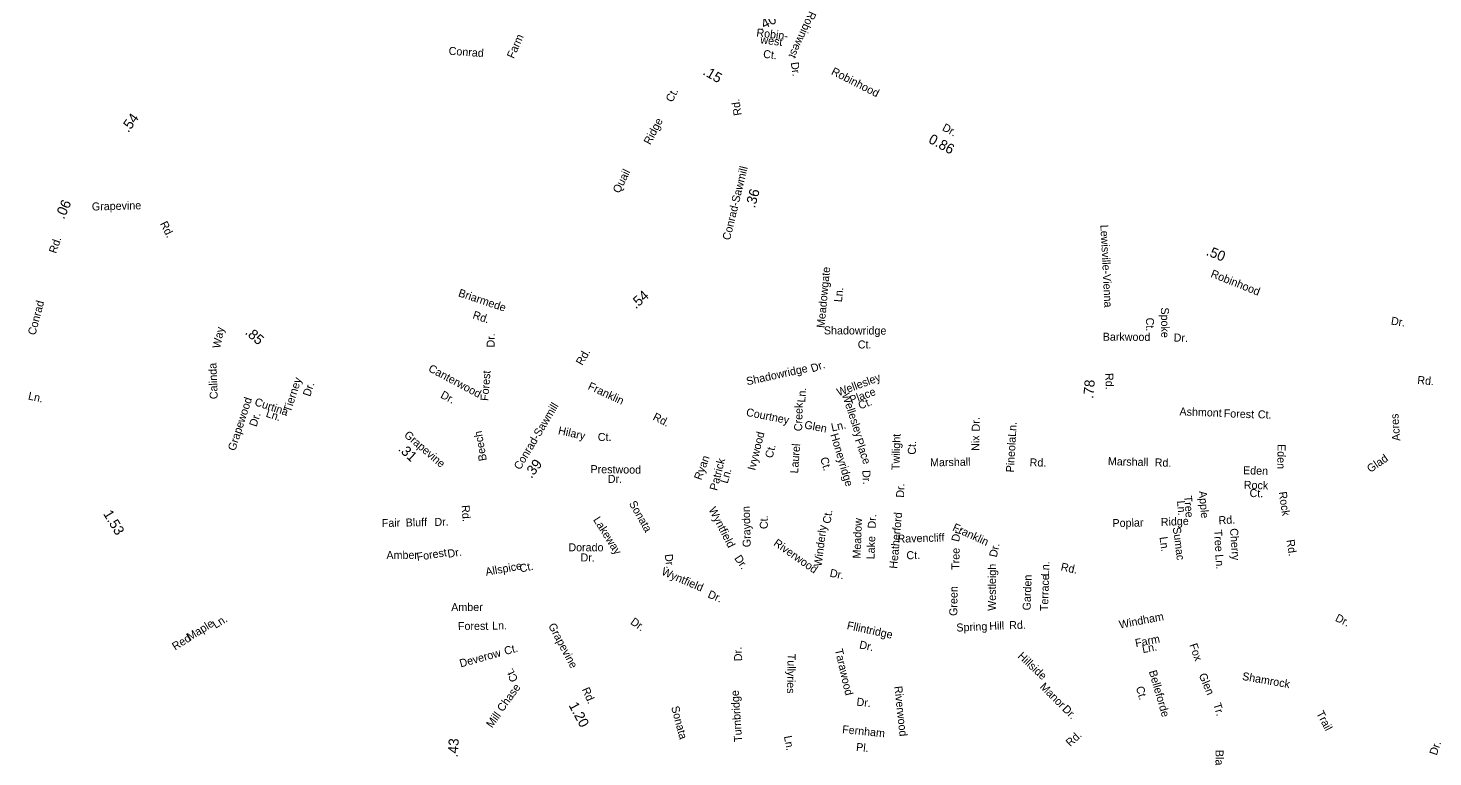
# Model space of a CAD drawing. Extents: x 1553981 to 1780076, y 812965 to 996873.
# Drawn here: x 1572723 to 1589400, y 860491 to 869138 of the extents above; entities that cross this region are included whole.
import ezdxf

# ---------------------------------------------------------------- set-up
doc = ezdxf.new("R2010")
doc.units = 0
for name, color, linetype in [('Exist Road Non-System Type 51 Label', 7, 'Continuous'), ('Exist Road Secondary Mileage Hundredths English Label', 7, 'Continuous'), ('Map Preparation Border Antique Large Shape', 7, 'Continuous')]:
    doc.layers.add(name, color=color, linetype=linetype)

msp = doc.modelspace()

# ---------------------------------------------------------------- texts
at = {"layer": 'Exist Road Non-System Type 51 Label'}
for s, rotation, p in [('Robinwest', 245.3077, (1581998, 869346)), ('Farm', 65.7589, (1578488, 868769)), ('Robin-', 353.2854, (1581365, 869040)), ('west', 353.2854, (1581412, 868956)), ('Conrad', 356.022, (1577713, 868822)), ('Ct.', 353.2854, (1581445, 868786)), ('Dr.', 278.3601, (1581776, 868728)), ('Ct.', 62.6106, (1580370, 868250)), ('Ridge', 62.6106, (1580109, 867746)), ('Quail', 63.271, (1579742, 867170)), ('Meadowgate', 84.6144, (1582177, 865577)), ('Briarmede', 341.5583, (1577822, 865957)), ('Ln.', 84.6144, (1582384, 865883)), ('Rd.', 341.5583, (1577993, 865696)), ('Ct.', 270.6383, (1585993, 865702)), ('Spoke', 270.6383, (1586171, 865823)), ('Way', 79.1093, (1575003, 865332)), ('Shadowridge', 359.7839, (1582170, 865504)), ('Barkwood', 359.6893, (1585480, 865429)), ('Dr.', 89.1918, (1578261, 865348)), ('Ct.', 359.7839, (1582572, 865337)), ('Dr.', 358.2564, (1586321, 865420)), ('Calinda', 92.263, (1574975, 864737)), ('Canterwood', 331.8045, (1577466, 865071)), ('Forest', 85.9186, (1578187, 864712)), ('Shadowridge', 12.4585, (1581260, 864899)), ('Dr.', 19.3359, (1582033, 865052)), ('Wellesley', 20.3364, (1582344, 864769)), ('Tierney', 71.9037, (1575840, 864573)), ('Dr.', 71.9037, (1576071, 864760)), ('Ln.', 85.7352, (1581947, 864693)), ('Place', 20.3364, (1582497, 864678)), ('Rd.', 355.2066, (1589212, 864917)), ('Ln.', 347.2521, (1572717, 864733)), ('Grapewood', 72.0844, (1575181, 864115)), ('Curtina', 341.3933, (1575404, 864665)), ('Dr.', 331.8045, (1577610, 864757)), ('Creek', 88.5322, (1581911, 864354)), ('Wellesley', 288.2796, (1582382, 864789)), ('Ct.', 20.3364, (1582598, 864612)), ('Dr.', 72.0844, (1575434, 864401)), ('Ln.', 341.3933, (1575538, 864529)), ('Courtney', 348.8709, (1581241, 864538)), ('Ashmont', 357.9772, (1586390, 864543)), ('Forest', 357.9772, (1586915, 864521)), ('Ct.', 357.9772, (1587320, 864509)), ('Acres', 93.9879, (1589012, 864243)), ('Beech', 99.8916, (1578169, 864010)), ('Hilary', 347.4371, (1579009, 864322)), ('Glen', 348.8709, (1581932, 864389)), ('Ln.', 12.3165, (1582267, 864351)), ('Dr.', 90.5323, (1584021, 864353)), ('Ln.', 86.7013, (1584449, 864286)), ('Ct.', 0.047, (1579486, 864239)), ('Ivywood', 75.9732, (1581353, 863884)), ('Laurel', 85.7352, (1581863, 863852)), ('Honeyridge', 286.4294, (1582247, 864314)), ('Place', 289.7339, (1582536, 864253)), ('Twilight', 88.2236, (1583067, 863893)), ('Ct.', 88.2236, (1583260, 864075)), ('Nix', 90.5323, (1584017, 864122)), ('Pineola', 86.7013, (1584425, 863864)), ('Eden', 269.2375, (1587556, 864203)), ('Ryan', 70.3005, (1580714, 863768)), ('Patrick', 75.654, (1580902, 863644)), ('Ct.', 75.9732, (1581560, 864029)), ('Ct.', 286.4294, (1582125, 864033)), ('Marshall', 0.8428, (1583431, 863938)), ('Rd.', 359.6662, (1584612, 863937)), ('Marshall', 358.4362, (1585540, 863953)), ('Rd.', 358.4362, (1586096, 863938)), ('Glad', 34.6243, (1588657, 863859)), ('Prestwood', 359.3098, (1579399, 863858)), ('Ln.', 73.9094, (1581026, 863728)), ('Dr.', 272.9873, (1582626, 863891)), ('Eden', 358.3031, (1587145, 863845)), ('Dr.', 0.2368, (1579605, 863742)), ('Dr.', 87.988, (1583121, 863565)), ('Rock', 358.3031, (1587154, 863672)), ('Sonata', 299.6774, (1579853, 863497)), ('Ln.', 274.8955, (1586362, 863528)), ('Tree', 274.8955, (1586444, 863587)), ('Apple', 274.8955, (1586621, 863643)), ('Ct.', 358.3031, (1587222, 863575)), ('Rock', 278.5941, (1587569, 863632)), ('Wyntfield', 297.166, (1580799, 863427)), ('Graydon', 91.3884, (1581302, 862980)), ('Ct.', 82.4173, (1582249, 863254)), ('Dr.', 87.8769, (1582785, 863199)), ('Heatherford', 84.9171, (1583040, 862721)), ('Rd.', 2.76, (1586857, 863251)), ('Fair', 1.1461, (1576923, 863218)), ('Bluff', 1.1461, (1577206, 863224)), ('Dr.', 1.1461, (1577547, 863231)), ('Lakeway', 302.3522, (1579427, 863304)), ('Ct.', 90.1456, (1581504, 863194)), ('Winderly', 83.0201, (1582143, 862745)), ('Meadow', 87.8769, (1582605, 862843)), ('Dr.', 76.2732, (1583772, 863036)), ('Poplar', 1.2672, (1585597, 863217)), ('Ridge', 2.4314, (1586171, 863230)), ('Sumac', 277.3291, (1586311, 863212)), ('Cherry', 273.5974, (1586991, 863201)), ('Dorado', 0.0634, (1579137, 862930)), ('Riverwood', 324.7897, (1581564, 863008)), ('Lake', 87.8769, (1582770, 862834)), ('Ravencliff', 1.6196, (1583045, 863032)), ('Ln.', 277.3291, (1586154, 863098)), ('Tree', 273.5974, (1586801, 863183)), ('Rd.', 278.9239, (1587661, 863063)), ('Amber', 0.3618, (1576977, 862838)), ('Forest', 9.0673, (1577343, 862816)), ('Dr.', 9.0673, (1577709, 862853)), ('Dr.', 359.6633, (1579281, 862810)), ('Dr.', 277.1126, (1580280, 862892)), ('Dr.', 303.9307, (1581103, 862847)), ('Ct.', 1.6196, (1583151, 862835)), ('Tree', 89.2062, (1583778, 862710)), ('Dr.', 78.1336, (1584222, 862854)), ('Ln.', 273.5974, (1586817, 862892)), ('Allspice', 10.3196, (1578161, 862638)), ('Ct.', 12.0728, (1578568, 862678)), ('Wyntfield', 336.8053, (1580234, 862656)), ('Dr.', 348.905, (1582234, 862630)), ('Westleigh', 89.6888, (1584211, 862224)), ('Ln.', 88.0922, (1584842, 862634)), ('Garden', 88.0922, (1584623, 862228)), ('Terrace', 88.0922, (1584830, 862219)), ('Dr.', 336.8053, (1580783, 862386)), ('Green', 89.1637, (1583753, 862163)), ('Amber', 0.3002, (1577746, 862220)), ('Dr.', 333.3888, (1588232, 862109)), ('Maple', 32.0833, (1574646, 861866)), ('Ln.', 32.0833, (1574949, 862010)), ('Forest', 0.3002, (1577826, 861996)), ('Ln.', 0.3002, (1578232, 862002)), ('Dr.', 324.8492, (1579865, 862074)), ('Fllintridge', 347.7366, (1582437, 862009)), ('Spring', 2.709, (1583745, 861977)), ('Hill', 2.709, (1584135, 861996)), ('Rd.', 1.6196, (1584371, 862006)), ('Windham', 10.893, (1585684, 862013)), ('Red', 32.0833, (1574469, 861751)), ('Dr.', 347.7366, (1582584, 861780)), ('Farm', 10.893, (1585874, 861793)), ('Deverow', 15.5458, (1577859, 861552)), ('Ct.', 15.1714, (1578389, 861699)), ('Dr.', 93.3057, (1581201, 861629)), ('Tullyries', 268.9025, (1581740, 861716)), ('Tarawood', 283.1264, (1582299, 861763)), ('Hillside', 316.8274, (1584464, 861677)), ('Ln.', 10.893, (1585957, 861722)), ('Fox', 289.0017, (1586508, 861820)), ('Ct.', 116.0318, (1578543, 861407)), ('Belleforde', 286.1335, (1586027, 861505)), ('Chase', 53.997, (1578358, 861019)), ('Manor', 314.9797, (1584726, 861316)), ('Glen', 292.8656, (1586618, 861462)), ('Shamrock', 350.0039, (1587130, 861405)), ('Turnbridge', 93.901, (1581200, 860672)), ('Dr.', 354.0044, (1582554, 861100)), ('Riverwood', 276.1599, (1583005, 861327)), ('Ct.', 286.1335, (1585873, 861315)), ('Mill', 53.997, (1578229, 860828)), ('Sonata', 284.8955, (1580356, 861081)), ('Dr.', 314.9797, (1584992, 861050)), ('Tr.', 286.9508, (1586790, 861116)), ('Trail', 297.739, (1588013, 861009)), ('Fernham', 354.4201, (1582384, 860773)), ('Ln.', 280.7833, (1581695, 860734)), ('Pl.', 354.4201, (1582549, 860563)), ('Blarney', 270, (1586819, 860574)), ('Dr.', 71.1165, (1589444, 860503))]:
    msp.add_text(s, height=95, rotation=rotation, dxfattribs=at).set_placement(p)
at = {"layer": 'Exist Road Secondary Mileage Hundredths English Label'}
for s, rotation, p in [('.40', 27.0644, (1581421, 869105)), ('.15', 329.6022, (1580724, 868593)), ('.54', 53.8443, (1573913, 867891)), ('0.86', 331.792, (1583402, 867783)), ('.36', 74.3021, (1581350, 866996)), ('.06', 65.8128, (1573148, 866863)), ('.50', 338.3247, (1586699, 866448)), ('.54', 42.3217, (1579938, 865799)), ('.85', 318.9254, (1575290, 865516)), ('.78', 84.8102, (1585367, 864739)), ('.31', 317.4495, (1577108, 864134)), ('.39', 52.3764, (1578698, 863788)), ('1.53', 300.9733, (1573610, 863377)), ('1.20', 298.0514, (1579137, 861104)), ('.43', 86.0726, (1577822, 860484))]:
    msp.add_text(s, height=120, rotation=rotation, dxfattribs=at).set_placement(p)
at = {"layer": 'Map Preparation Border Antique Large Shape'}
for s, rotation, p in [('Robinhood', 333.0284, (1582249, 868593)), ('Rd.', 98.9522, (1581195, 868107)), ('Dr.', 331.3367, (1583566, 867930)), ('Conrad-Sawmill', 76.3405, (1581055, 866615)), ('Grapevine', 1.5443, (1573481, 866973)), ('Rd.', 297.0569, (1574286, 866817)), ('Lewisville-Vienna', 272.8577, (1585452, 866802)), ('Rd.', 71.2595, (1573056, 866457)), ('Robinhood', 338.347, (1586754, 866188)), ('Conrad', 75.3069, (1572809, 865488)), ('Dr.', 351.2612, (1588897, 865621)), ('Rd.', 59.7404, (1579301, 865128)), ('Rd.', 271.9642, (1585510, 865044)), ('Franklin', 335.0278, (1579360, 864857)), ('Conrad-Sawmill', 59.1817, (1578564, 863889)), ('Rd.', 332.9354, (1580131, 864495)), ('Grapevine', 319.4299, (1577179, 864297)), ('Rd.', 274.2126, (1577868, 863475)), ('Franklin', 335.0278, (1583689, 863182)), ('Rd.', 348.1255, (1584976, 862704)), ('Grapevine', 297.8373, (1578895, 862049)), ('Rd.', 293.79, (1579295, 861292)), ('Rd.', 42.8862, (1585095, 860606))]:
    msp.add_text(s, height=95, rotation=rotation, dxfattribs=at).set_placement(p)

doc.saveas('drawing.dxf')
